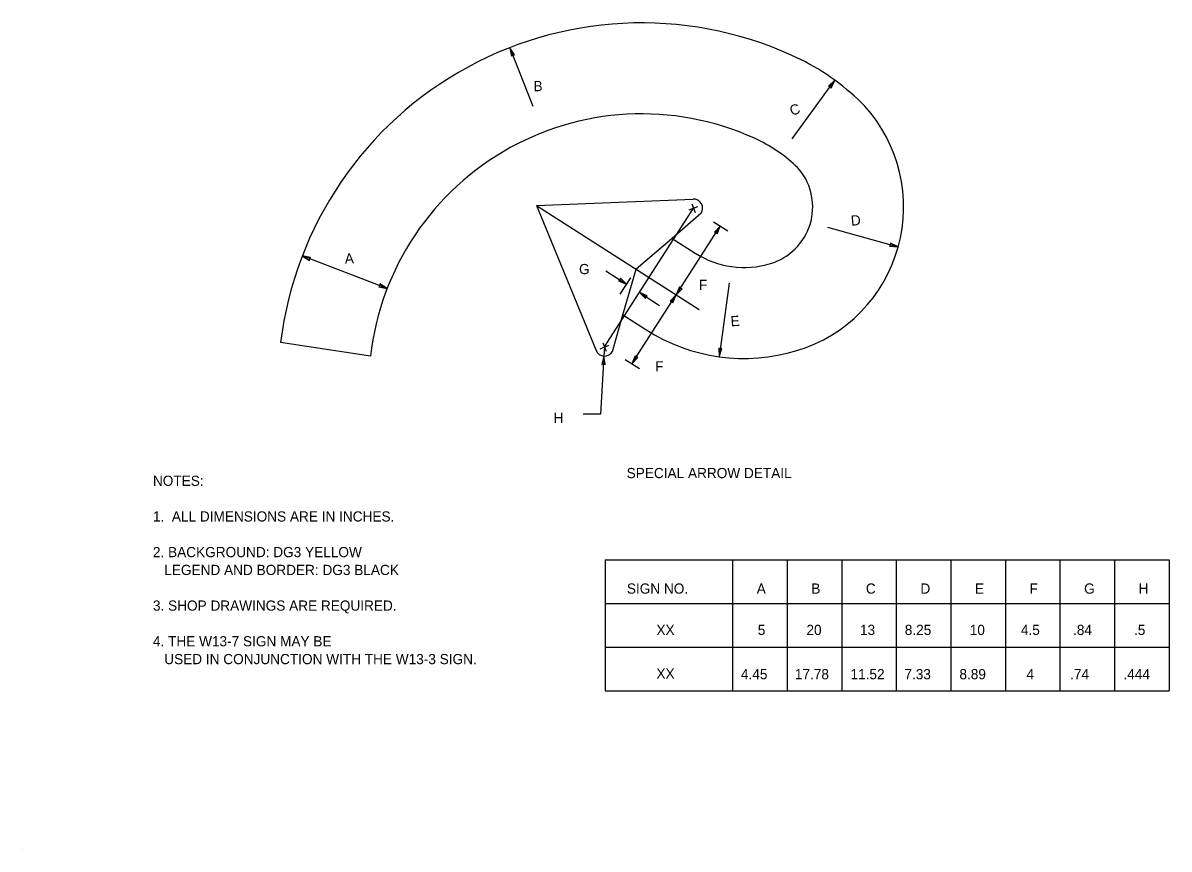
# Model space of a CAD drawing. Extents: x 582908 to 586040, y 1530940 to 1533040.
# Drawn here: x 582908 to 584484, y 1530940 to 1532075 of the extents above; entities that cross this region are included whole.
import ezdxf

# ---------------------------------------------------------------- set-up
doc = ezdxf.new("R2010")
doc.units = 0
for name, color, linetype in [('AdhocPoint_dp', 7, 'Continuous'), ('GSDims', 7, 'Continuous'), ('SignDetail', 7, 'Continuous'), ('TextLabel', 7, 'Continuous'), ('TextNotes', 7, 'Continuous'), ('TextTables', 7, 'Continuous')]:
    doc.layers.add(name, color=color, linetype=linetype)

msp = doc.modelspace()

# ---------------------------------------------------------------- linework, layer by layer
at = {"layer": 'AdhocPoint_dp'}
msp.add_line((582908.3, 1530939.8), (582908.3, 1530939.8), dxfattribs=at)
at = {"layer": 'GSDims'}
for p, q in [((583577.5, 1532040.8), (583609.1, 1531960.6)), ((583577.5, 1532040.8), (583579.7, 1532029.2)), ((583583.8, 1532030.8), (583577.5, 1532040.8)), ((583579.7, 1532029.2), (583581.4, 1532030.9)), ((583581.4, 1532030.9), (583583.8, 1532030.8)), ((583965.6, 1531915.4), (584024.4, 1531996.1)), ((584024.4, 1531996.1), (584015.8, 1531988)), ((584015.8, 1531988), (584018.1, 1531987.4)), ((584018.1, 1531987.4), (584019.3, 1531985.4)), ((584019.3, 1531985.4), (584024.4, 1531996.1)), ((583824.3, 1531818.1), (583835.9, 1531822.8)), ((583827.8, 1531826.2), (583832.4, 1531814.6)), ((583857.6, 1531801.8), (583877.2, 1531789.3)), ((583806.2, 1531701.1), (583866.9, 1531795.8)), ((583866.9, 1531795.8), (583858.8, 1531787.3)), ((583858.8, 1531787.3), (583861.1, 1531786.8)), ((583861.1, 1531786.8), (583862.5, 1531784.9)), ((583862.5, 1531784.9), (583866.9, 1531795.8)), ((584014.2, 1531794.2), (584111.4, 1531767.2)), ((584101, 1531770), (584099.6, 1531768.2)), ((584099.6, 1531768.2), (584111.4, 1531767.2)), ((584111.4, 1531767.2), (584100.8, 1531772.4)), ((584100.8, 1531772.4), (584101, 1531770)), ((583409, 1531710), (583292.2, 1531754.7)), ((583292.2, 1531754.7), (583302.3, 1531748.5)), ((583303.8, 1531752.6), (583292.2, 1531754.7)), ((583302.3, 1531750.9), (583303.8, 1531752.6)), ((583302.3, 1531748.5), (583302.3, 1531750.9)), ((583709.5, 1531734.2), (583738, 1531715.8)), ((583729, 1531721.6), (583727.1, 1531720.3)), ((583727.1, 1531720.3), (583738, 1531715.8)), ((583729.5, 1531724), (583729, 1531721.6)), ((583729.3, 1531702.2), (583743.7, 1531724.7)), ((583738, 1531715.8), (583729.5, 1531724)), ((583879.3, 1531717.5), (583865.3, 1531616.3)), ((583399, 1531713.9), (583397.4, 1531712.2)), ((583397.4, 1531712.2), (583409, 1531710)), ((583409, 1531710), (583398.9, 1531716.3)), ((583398.9, 1531716.3), (583399, 1531713.9)), ((583755.7, 1531704.5), (583783.2, 1531686.8)), ((583755.7, 1531704.5), (583764.3, 1531696.3)), ((583766.6, 1531700), (583755.7, 1531704.5)), ((583810.6, 1531712.1), (583806.2, 1531701.1)), ((583806.2, 1531701.1), (583814.3, 1531709.7)), ((583812, 1531710.1), (583810.6, 1531712.1)), ((583814.3, 1531709.7), (583812, 1531710.1)), ((583745.4, 1531606.4), (583806.2, 1531701.1)), ((583764.3, 1531696.3), (583764.7, 1531698.7)), ((583764.7, 1531698.7), (583766.6, 1531700)), ((583806.2, 1531701.1), (583798, 1531692.6)), ((583798, 1531692.6), (583800.4, 1531692.1)), ((583800.4, 1531692.1), (583801.7, 1531690.2)), ((583801.7, 1531690.2), (583806.2, 1531701.1)), ((583701.9, 1531627.3), (583713.5, 1531632)), ((583705.4, 1531635.4), (583710, 1531623.8)), ((583707.7, 1531629.6), (583707, 1531617.2)), ((583866.8, 1531626.9), (583864.7, 1531628.1)), ((583864.7, 1531628.1), (583865.3, 1531616.3)), ((583865.3, 1531616.3), (583869.1, 1531627.5)), ((583869.1, 1531627.5), (583866.8, 1531626.9)), ((583707, 1531617.2), (583702.4, 1531537.3)), ((583707, 1531617.2), (583704.1, 1531605.7)), ((583708.5, 1531605.5), (583707, 1531617.2)), ((583736.2, 1531612.4), (583755.7, 1531599.9)), ((583749.9, 1531617.4), (583745.4, 1531606.4)), ((583745.4, 1531606.4), (583753.6, 1531615)), ((583751.2, 1531615.5), (583749.9, 1531617.4)), ((583753.6, 1531615), (583751.2, 1531615.5)), ((583704.1, 1531605.7), (583706.4, 1531606.5)), ((583706.4, 1531606.5), (583708.5, 1531605.5)), ((583702.4, 1531537.3), (583678.6, 1531537.3))]:
    msp.add_line(p, q, dxfattribs=at)
at = {"layer": 'SignDetail'}
for p, q in [((583614.3, 1531824.2), (583829.4, 1531832.9)), ((583614.3, 1531824.2), (583837.7, 1531680.9)), ((583614.3, 1531824.2), (583696.1, 1531624.9)), ((583707.7, 1531629.6), (583830.1, 1531820.4)), ((583840.1, 1531813), (583800.6, 1531778.9)), ((583800.6, 1531778.9), (583751.2, 1531736.4)), ((583800.6, 1531778.9), (583832.2, 1531758.7)), ((583733.1, 1531673.7), (583751.2, 1531736.4)), ((583718.7, 1531623.6), (583733.1, 1531673.7)), ((583733.1, 1531673.7), (583764.7, 1531653.5)), ((583386.1, 1531616.8), (583262.5, 1531635.6))]:
    msp.add_line(p, q, dxfattribs=at)
for centre, radius, start, end in [((583758.8, 1531574.9), 500, 64.0026, 173.0199), ((583833.6, 1531734.2), 324, 44.3092, 63.5547), ((583912.6, 1531822.1), 206.3, 286.8096, 42.1395), ((583758.8, 1531574.9), 375, 64.0026, 173.5767), ((583833.6, 1531734.2), 198.9, 44.3092, 63.5547), ((583912.6, 1531822.1), 81.3, 286.8096, 38.803), ((583829.9, 1531820.3), 12.6, 324.4393, 92.3246), ((583899.7, 1531863.9), 125, 237.3246, 286.8677), ((583899.7, 1531863.9), 250, 237.3246, 286.8677), ((583707.7, 1531629.6), 12.5, 202.3246, 331.1534)]:
    msp.add_arc(centre, radius, start, end, dxfattribs=at)
at = {"layer": 'TextTables'}
for p, q in [((583708.8, 1531337.2), (583708.8, 1531157.2)), ((583708.8, 1531337.2), (584483.8, 1531337.2)), ((583883.8, 1531337.2), (583883.8, 1531157.2)), ((583958.8, 1531337.2), (583958.8, 1531157.2)), ((584033.8, 1531337.2), (584033.8, 1531157.2)), ((584108.8, 1531337.2), (584108.8, 1531157.2)), ((584183.8, 1531337.2), (584183.8, 1531157.2)), ((584258.8, 1531337.2), (584258.8, 1531157.2)), ((584333.8, 1531337.2), (584333.8, 1531157.2)), ((584408.8, 1531337.2), (584408.8, 1531157.2)), ((584483.8, 1531337.2), (584483.8, 1531157.2)), ((583708.8, 1531277.2), (584483.8, 1531277.2)), ((583708.8, 1531217.2), (584483.8, 1531217.2)), ((583708.8, 1531157.2), (584483.8, 1531157.2))]:
    msp.add_line(p, q, dxfattribs=at)

# ---------------------------------------------------------------- texts
at = {"layer": 'GSDims'}
for s, rotation, p in [('B', 359.8433, (583610.1, 1531981.1)), ('C', 20.0634, (583965.4, 1531947)), ('D', 5.3645, (584047, 1531796.1)), ('A', 2.778, (583351, 1531744)), ('G', 359.8433, (583672.7, 1531729.7)), ('F', 359.8433, (583837.5, 1531708)), ('E', 3.8579, (583881.5, 1531657.9)), ('F', 359.8433, (583777.4, 1531596.1)), ('H', 359.8433, (583637.8, 1531525.2))]:
    msp.add_text(s, height=14, rotation=rotation, dxfattribs=at).set_placement(p)
at = {"layer": 'TextLabel'}
msp.add_text('SPECIAL ARROW DETAIL', height=14, dxfattribs=at).set_placement((583738.2, 1531449.4))
at = {"layer": 'TextNotes'}
for s, p in [('NOTES:', (583087, 1531438.8)), ('1.  ALL DIMENSIONS ARE IN INCHES.', (583087, 1531389.8)), ('2. BACKGROUND: DG3 YELLOW ', (583087, 1531340.8)), ('   LEGEND AND BORDER: DG3 BLACK', (583087, 1531316.3)), ('3. SHOP DRAWINGS ARE REQUIRED.', (583087, 1531267.3)), ('4. THE W13-7 SIGN MAY BE', (583087, 1531218.3)), ('   USED IN CONJUNCTION WITH THE W13-3 SIGN.', (583087, 1531193.8))]:
    msp.add_text(s, height=14, dxfattribs=at).set_placement(p)
at = {"layer": 'TextTables'}
for s, p in [('SIGN NO.', (583738.5, 1531290.7)), ('A', (583917, 1531290.7)), ('B', (583992, 1531290.7)), ('C', (584067, 1531290.7)), ('D', (584142, 1531290.7)), ('E', (584217, 1531290.7)), ('F', (584292, 1531290.7)), ('G', (584367, 1531290.7)), ('H', (584442, 1531290.7)), ('XX', (583779.1, 1531233.9)), ('5', (583918.4, 1531233.9)), ('20', (583985.3, 1531233.9)), ('13', (584058.9, 1531233.9)), ('8.25', (584120.5, 1531233.9)), ('10', (584209.8, 1531233.9)), ('4.5', (584280.1, 1531233.9)), ('.84', (584351.8, 1531233.9)), ('.5', (584435.6, 1531233.9)), ('XX', (583779.1, 1531173.9)), ('4.45', (583895.3, 1531173.1)), ('17.78', (583969.4, 1531173.1)), ('11.52', (584045.9, 1531173.1)), ('7.33', (584120, 1531173.1)), ('8.89', (584195.6, 1531173.1)), ('4', (584287.8, 1531173.1)), ('.74', (584347.8, 1531173.1)), ('.444', (584421.1, 1531173.1))]:
    msp.add_text(s, height=14, dxfattribs=at).set_placement(p)

doc.saveas('drawing.dxf')
